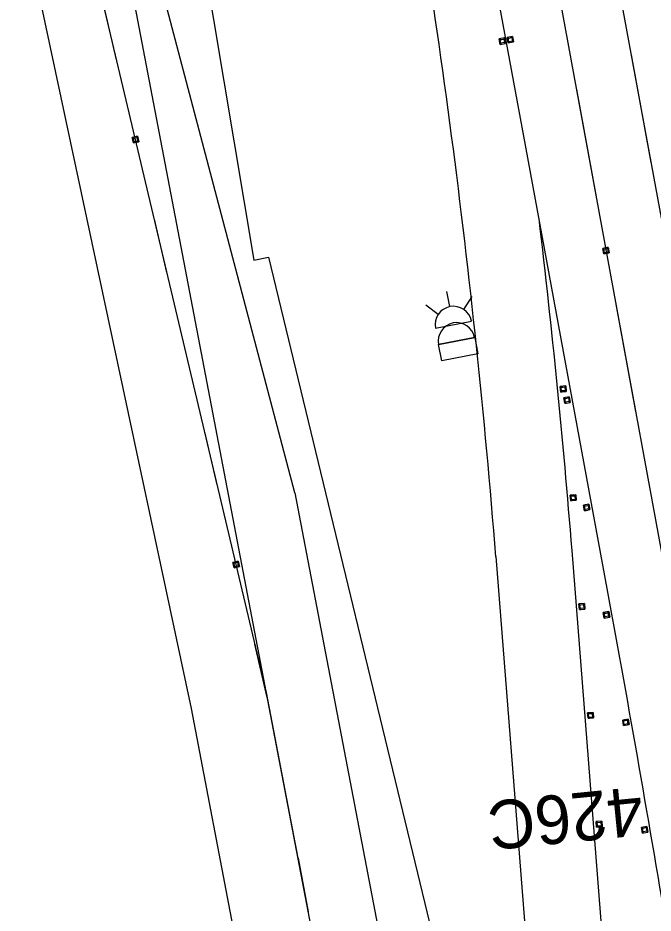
# Model space of a CAD drawing. Extents: x 2471014 to 2497726, y 6959577 to 6980268.
# Drawn here: x 2488313.2 to 2488429.6, y 6962894.6 to 6963058.6 of the extents above; entities that cross this region are included whole.
import ezdxf

# ---------------------------------------------------------------- set-up
doc = ezdxf.new("R2010")
doc.units = 0
for name, color, linetype in [('1', 7, 'Continuous'), ('13', 7, 'Continuous'), ('18', 7, 'Continuous'), ('23', 7, 'Continuous'), ('25', 7, 'Continuous'), ('5', 7, 'Continuous'), ('C-ANNO-NOTE', 7, 'Continuous'), ('C-COMM-STRC', 7, 'Continuous'), ('PMK_Pav_Mark_Wht_Number', 7, 'Continuous'), ('RDWY_PAVE_XSTREET_FOC', 7, 'Continuous'), ('V7_25', 7, 'Continuous'), ('V7_50', 7, 'Continuous')]:
    doc.layers.add(name, color=color, linetype=linetype)

msp = doc.modelspace()

# ---------------------------------------------------------------- linework, layer by layer
at = {"layer": '1'}
for p, q in [((2488331.27, 6963050.93), (2488328.96, 6963060.66)), ((2488340.48, 6963012), (2488338.18, 6963021.74)), ((2488349.7, 6962973.08), (2488347.4, 6962982.81)), ((2488358.88, 6962934.15), (2488356.61, 6962943.89)), ((2488364.5, 6962904.68), (2488366.38, 6962894.86))]:
    msp.add_line(p, q, dxfattribs=at)
at = {"layer": '13'}
for q in [(2488338.38, 6963068.57), (2488382.89, 6962872.4)]:
    msp.add_line((2488363.93, 6962971.65), q, dxfattribs=at)
at = {"layer": '18'}
for p, q in [((2488345.01, 6962932.12), (2488316.74, 6963064.61)), ((2488400.75, 6962959.93), (2488406.46, 6962887.6)), ((2488357.35, 6962867.52), (2488345.01, 6962932.12))]:
    msp.add_line(p, q, dxfattribs=at)
msp.add_arc((2486905.4, 6962841.87), 1500, 4.51393, 10.43537, dxfattribs=at)
at = {"layer": '23'}
for p, q in [((2488403.81, 6963055.23), (2488402.81, 6963055.05)), ((2488403.67, 6963055.04), (2488403.81, 6963055.23)), ((2488403.81, 6963055.23), (2488403.99, 6963054.24)), ((2488402.33, 6963054.96), (2488401.34, 6963054.78)), ((2488401.52, 6963053.78), (2488401.34, 6963054.78)), ((2488401.34, 6963054.78), (2488401.52, 6963054.64)), ((2488401.52, 6963054.64), (2488401.66, 6963054.67)), ((2488401.65, 6963053.98), (2488401.52, 6963053.78)), ((2488401.52, 6963053.78), (2488401.79, 6963053.83)), ((2488402.31, 6963054.1), (2488401.65, 6963053.98)), ((2488401.66, 6963054.67), (2488402.19, 6963054.76)), ((2488401.79, 6963053.83), (2488402.52, 6963053.97)), ((2488402.19, 6963054.76), (2488402.33, 6963054.96)), ((2488402.52, 6963053.97), (2488402.31, 6963054.1)), ((2488402.33, 6963054.96), (2488402.52, 6963053.97)), ((2488403, 6963054.05), (2488402.81, 6963055.05)), ((2488402.81, 6963055.05), (2488403, 6963054.91)), ((2488403, 6963054.91), (2488403.14, 6963054.94)), ((2488403.12, 6963054.25), (2488403, 6963054.05)), ((2488403, 6963054.05), (2488403.26, 6963054.1)), ((2488403.79, 6963054.37), (2488403.12, 6963054.25)), ((2488403.14, 6963054.94), (2488403.67, 6963055.04)), ((2488403.26, 6963054.1), (2488403.99, 6963054.24)), ((2488403.99, 6963054.24), (2488403.79, 6963054.37)), ((2488335.11, 6963036.94), (2488334.12, 6963036.71)), ((2488334.36, 6963035.72), (2488334.12, 6963036.71)), ((2488334.12, 6963036.71), (2488334.32, 6963036.58)), ((2488334.32, 6963036.58), (2488334.46, 6963036.62)), ((2488334.47, 6963035.92), (2488334.36, 6963035.72)), ((2488334.36, 6963035.72), (2488334.62, 6963035.79)), ((2488334.46, 6963036.62), (2488334.98, 6963036.74)), ((2488335.13, 6963036.08), (2488334.47, 6963035.92)), ((2488334.62, 6963035.79), (2488335.34, 6963035.96)), ((2488334.98, 6963036.74), (2488335.11, 6963036.94)), ((2488335.11, 6963036.94), (2488335.34, 6963035.96)), ((2488335.34, 6963035.96), (2488335.13, 6963036.08)), ((2488421.06, 6963016.55), (2488420.33, 6963016.41)), ((2488420.51, 6963015.42), (2488420.33, 6963016.41)), ((2488420.33, 6963016.41), (2488420.54, 6963016.28)), ((2488420.54, 6963016.28), (2488421.2, 6963016.4)), ((2488421.33, 6963016.6), (2488421.06, 6963016.55)), ((2488421.2, 6963016.4), (2488421.33, 6963016.6)), ((2488421.33, 6963016.6), (2488421.51, 6963015.6)), ((2488420.66, 6963015.62), (2488420.51, 6963015.42)), ((2488420.51, 6963015.42), (2488421.51, 6963015.6)), ((2488421.19, 6963015.71), (2488420.66, 6963015.62)), ((2488421.32, 6963015.74), (2488421.19, 6963015.71)), ((2488421.51, 6963015.6), (2488421.32, 6963015.74)), ((2488413.55, 6962991.2), (2488412.54, 6962991.1)), ((2488413.39, 6962991.02), (2488413.55, 6962991.2)), ((2488413.55, 6962991.2), (2488413.65, 6962990.19)), ((2488412.64, 6962990.09), (2488412.54, 6962991.1)), ((2488412.54, 6962991.1), (2488412.71, 6962990.95)), ((2488412.78, 6962990.28), (2488412.64, 6962990.09)), ((2488412.64, 6962990.09), (2488412.9, 6962990.12)), ((2488412.71, 6962990.95), (2488412.85, 6962990.96)), ((2488413.45, 6962990.34), (2488412.78, 6962990.28)), ((2488412.85, 6962990.96), (2488413.39, 6962991.02)), ((2488412.9, 6962990.12), (2488413.65, 6962990.19)), ((2488413.65, 6962990.19), (2488413.45, 6962990.34)), ((2488414.19, 6962989.2), (2488413.19, 6962989.02)), ((2488413.38, 6962988.02), (2488413.19, 6962989.02)), ((2488413.19, 6962989.02), (2488413.38, 6962988.88)), ((2488413.38, 6962988.88), (2488413.52, 6962988.91)), ((2488413.5, 6962988.21), (2488413.38, 6962988.02)), ((2488413.38, 6962988.02), (2488413.64, 6962988.07)), ((2488414.17, 6962988.34), (2488413.5, 6962988.21)), ((2488413.52, 6962988.91), (2488414.05, 6962989)), ((2488413.64, 6962988.07), (2488414.38, 6962988.2)), ((2488414.05, 6962989), (2488414.19, 6962989.2)), ((2488414.38, 6962988.2), (2488414.17, 6962988.34)), ((2488414.19, 6962989.2), (2488414.38, 6962988.2)), ((2488415.39, 6962971.28), (2488414.38, 6962971.19)), ((2488414.46, 6962970.18), (2488414.38, 6962971.19)), ((2488414.38, 6962971.19), (2488414.55, 6962971.04)), ((2488414.61, 6962970.36), (2488414.46, 6962970.18)), ((2488414.46, 6962970.18), (2488414.73, 6962970.21)), ((2488414.55, 6962971.04), (2488414.69, 6962971.05)), ((2488415.28, 6962970.42), (2488414.61, 6962970.36)), ((2488414.69, 6962971.05), (2488415.22, 6962971.1)), ((2488414.73, 6962970.21), (2488415.47, 6962970.27)), ((2488415.22, 6962971.1), (2488415.39, 6962971.28)), ((2488415.47, 6962970.27), (2488415.28, 6962970.42)), ((2488415.39, 6962971.28), (2488415.47, 6962970.27)), ((2488417.81, 6962969.53), (2488416.82, 6962969.35)), ((2488417, 6962968.35), (2488416.82, 6962969.35)), ((2488416.82, 6962969.35), (2488417, 6962969.21)), ((2488417, 6962969.21), (2488417.14, 6962969.24)), ((2488417.13, 6962968.55), (2488417, 6962968.35)), ((2488417, 6962968.35), (2488417.27, 6962968.4)), ((2488417.79, 6962968.67), (2488417.13, 6962968.55)), ((2488417.14, 6962969.24), (2488417.67, 6962969.33)), ((2488417.27, 6962968.4), (2488418, 6962968.54)), ((2488417.67, 6962969.33), (2488417.81, 6962969.53)), ((2488418, 6962968.54), (2488417.79, 6962968.67)), ((2488417.81, 6962969.53), (2488418, 6962968.54)), ((2488353.54, 6962959.1), (2488352.55, 6962958.86)), ((2488352.79, 6962957.88), (2488352.55, 6962958.86)), ((2488352.55, 6962958.86), (2488352.75, 6962958.74)), ((2488352.75, 6962958.74), (2488352.89, 6962958.77)), ((2488352.89, 6962958.77), (2488353.41, 6962958.89)), ((2488353.41, 6962958.89), (2488353.54, 6962959.1)), ((2488353.54, 6962959.1), (2488353.78, 6962958.11)), ((2488352.9, 6962958.08), (2488352.79, 6962957.88)), ((2488352.79, 6962957.88), (2488353.05, 6962957.94)), ((2488353.56, 6962958.23), (2488352.9, 6962958.08)), ((2488353.05, 6962957.94), (2488353.78, 6962958.11)), ((2488353.78, 6962958.11), (2488353.56, 6962958.23)), ((2488416.99, 6962951.34), (2488415.98, 6962951.26)), ((2488416.06, 6962950.25), (2488415.98, 6962951.26)), ((2488415.98, 6962951.26), (2488416.16, 6962951.11)), ((2488416.21, 6962950.43), (2488416.06, 6962950.25)), ((2488416.06, 6962950.25), (2488416.33, 6962950.27)), ((2488416.16, 6962951.11), (2488416.3, 6962951.12)), ((2488416.88, 6962950.48), (2488416.21, 6962950.43)), ((2488416.3, 6962951.12), (2488416.83, 6962951.16)), ((2488416.33, 6962950.27), (2488417.07, 6962950.33)), ((2488416.83, 6962951.16), (2488416.99, 6962951.34)), ((2488417.07, 6962950.33), (2488416.88, 6962950.48)), ((2488416.99, 6962951.34), (2488417.07, 6962950.33)), ((2488421.44, 6962949.86), (2488420.44, 6962949.68)), ((2488420.62, 6962948.68), (2488420.44, 6962949.68)), ((2488420.44, 6962949.68), (2488420.63, 6962949.54)), ((2488420.75, 6962948.88), (2488420.62, 6962948.68)), ((2488420.62, 6962948.68), (2488420.89, 6962948.73)), ((2488420.63, 6962949.54), (2488420.76, 6962949.57)), ((2488421.41, 6962949), (2488420.75, 6962948.88)), ((2488420.76, 6962949.57), (2488421.29, 6962949.66)), ((2488420.89, 6962948.73), (2488421.62, 6962948.87)), ((2488421.29, 6962949.66), (2488421.44, 6962949.86)), ((2488421.62, 6962948.87), (2488421.41, 6962949)), ((2488421.44, 6962949.86), (2488421.62, 6962948.87)), ((2488418.57, 6962931.4), (2488417.56, 6962931.32)), ((2488417.64, 6962930.31), (2488417.56, 6962931.32)), ((2488417.56, 6962931.32), (2488417.73, 6962931.17)), ((2488417.73, 6962931.17), (2488417.87, 6962931.18)), ((2488418.46, 6962930.55), (2488417.78, 6962930.49)), ((2488417.87, 6962931.18), (2488418.41, 6962931.22)), ((2488418.41, 6962931.22), (2488418.57, 6962931.4)), ((2488418.65, 6962930.39), (2488418.46, 6962930.55)), ((2488418.57, 6962931.4), (2488418.65, 6962930.39)), ((2488417.78, 6962930.49), (2488417.64, 6962930.31)), ((2488417.64, 6962930.31), (2488417.91, 6962930.33)), ((2488417.91, 6962930.33), (2488418.65, 6962930.39)), ((2488424.99, 6962930.18), (2488423.99, 6962930)), ((2488424.16, 6962929), (2488423.99, 6962930)), ((2488423.99, 6962930), (2488424.17, 6962929.86)), ((2488424.29, 6962929.19), (2488424.16, 6962929)), ((2488424.16, 6962929), (2488424.43, 6962929.05)), ((2488424.17, 6962929.86), (2488424.31, 6962929.89)), ((2488424.96, 6962929.31), (2488424.29, 6962929.19)), ((2488424.31, 6962929.89), (2488424.84, 6962929.98)), ((2488424.43, 6962929.05), (2488425.16, 6962929.18)), ((2488424.84, 6962929.98), (2488424.99, 6962930.18)), ((2488425.16, 6962929.18), (2488424.96, 6962929.31)), ((2488424.99, 6962930.18), (2488425.16, 6962929.18)), ((2488420.14, 6962911.47), (2488419.13, 6962911.39)), ((2488419.21, 6962910.37), (2488419.13, 6962911.39)), ((2488419.13, 6962911.39), (2488419.3, 6962911.23)), ((2488419.3, 6962911.23), (2488419.44, 6962911.24)), ((2488419.44, 6962911.24), (2488419.98, 6962911.28)), ((2488419.98, 6962911.28), (2488420.14, 6962911.47)), ((2488420.14, 6962911.47), (2488420.22, 6962910.45)), ((2488419.36, 6962910.55), (2488419.21, 6962910.37)), ((2488419.21, 6962910.37), (2488419.48, 6962910.4)), ((2488420.03, 6962910.61), (2488419.36, 6962910.55)), ((2488419.48, 6962910.4), (2488420.22, 6962910.45)), ((2488420.22, 6962910.45), (2488420.03, 6962910.61)), ((2488428.43, 6962910.47), (2488427.43, 6962910.3)), ((2488427.6, 6962909.3), (2488427.43, 6962910.3)), ((2488427.43, 6962910.3), (2488427.61, 6962910.16)), ((2488427.73, 6962909.49), (2488427.6, 6962909.3)), ((2488427.6, 6962909.3), (2488427.87, 6962909.35)), ((2488427.61, 6962910.16), (2488427.75, 6962910.19)), ((2488428.4, 6962909.61), (2488427.73, 6962909.49)), ((2488427.75, 6962910.19), (2488428.28, 6962910.28)), ((2488427.87, 6962909.35), (2488428.6, 6962909.47)), ((2488428.28, 6962910.28), (2488428.43, 6962910.47)), ((2488428.6, 6962909.47), (2488428.4, 6962909.61)), ((2488428.43, 6962910.47), (2488428.6, 6962909.47))]:
    msp.add_line(p, q, dxfattribs=at)
for points in [[(2488401.65, 6963053.98), (2488401.52, 6963054.64), (2488402.19, 6963054.76), (2488402.31, 6963054.1)], [(2488403.12, 6963054.25), (2488403, 6963054.91), (2488403.67, 6963055.04), (2488403.79, 6963054.37)], [(2488334.47, 6963035.92), (2488334.32, 6963036.58), (2488334.98, 6963036.74), (2488335.13, 6963036.08)], [(2488421.2, 6963016.4), (2488421.32, 6963015.74), (2488420.66, 6963015.62), (2488420.54, 6963016.28)], [(2488412.78, 6962990.28), (2488412.71, 6962990.95), (2488413.39, 6962991.02), (2488413.45, 6962990.34)], [(2488413.5, 6962988.21), (2488413.38, 6962988.88), (2488414.05, 6962989), (2488414.17, 6962988.34)], [(2488414.61, 6962970.36), (2488414.55, 6962971.04), (2488415.22, 6962971.1), (2488415.28, 6962970.42)], [(2488417.13, 6962968.55), (2488417, 6962969.21), (2488417.67, 6962969.33), (2488417.79, 6962968.67)], [(2488352.9, 6962958.08), (2488352.75, 6962958.74), (2488353.41, 6962958.89), (2488353.56, 6962958.23)], [(2488416.21, 6962950.43), (2488416.16, 6962951.11), (2488416.83, 6962951.16), (2488416.88, 6962950.48)], [(2488420.75, 6962948.88), (2488420.63, 6962949.54), (2488421.29, 6962949.66), (2488421.41, 6962949)], [(2488417.78, 6962930.49), (2488417.73, 6962931.17), (2488418.41, 6962931.22), (2488418.46, 6962930.55)], [(2488424.29, 6962929.19), (2488424.17, 6962929.86), (2488424.84, 6962929.98), (2488424.96, 6962929.31)], [(2488419.36, 6962910.55), (2488419.3, 6962911.23), (2488419.98, 6962911.28), (2488420.03, 6962910.61)], [(2488427.73, 6962909.49), (2488427.61, 6962910.16), (2488428.28, 6962910.28), (2488428.4, 6962909.61)]]:
    msp.add_lwpolyline(points, close=True, dxfattribs=at)
at = {"layer": '25'}
for p, q in [((2488421.28, 6962953.41), (2488406.19, 6963035.33)), ((2488420.32, 6962889.91), (2488414.71, 6962961.03))]:
    msp.add_line(p, q, dxfattribs=at)
for centre, radius, start, end in [((2486905.4, 6962841.87), 1514, 4.51393, 6.82786), ((2484825.75, 6962291.21), 3656, 9.41605, 10.43537)]:
    msp.add_arc(centre, radius, start, end, dxfattribs=at)
at = {"layer": '5'}
msp.add_line((2488406.19, 6963035.33), (2488351.85, 6963330.37), dxfattribs=at)
at = {"layer": 'C-ANNO-NOTE'}
msp.add_line((2488371.12, 6962870.04), (2488281.3, 6963340.31), dxfattribs=at)
at = {"layer": 'C-COMM-STRC'}
for p, q in [((2488392.34, 6963005.75), (2488391.8, 6963008.51)), ((2488390.18, 6963004.32), (2488387.92, 6963005.98)), ((2488394.87, 6963005.23), (2488396.41, 6963007.58)), ((2488389.67, 6963001.79), (2488396.3, 6963003.08)), ((2488396.88, 6963000.08), (2488390.25, 6962998.79)), ((2488390.25, 6962998.79), (2488396.88, 6963000.08))]:
    msp.add_line(p, q, dxfattribs=at)
msp.add_lwpolyline([(2488396.88, 6963000.08), (2488397.46, 6962997.08), (2488390.83, 6962995.79), (2488390.25, 6962998.79)], close=True, dxfattribs=at)
for centre in [(2488392.98, 6963002.43), (2488393.56, 6962999.43)]:
    msp.add_arc(centre, 3.37, 10.983, 190.983, dxfattribs=at)
at = {"layer": 'RDWY_PAVE_XSTREET_FOC'}
for p, q in [((2488425.52, 6963051.84), (2488429.14, 6963032.17)), ((2488415.5, 6963045.51), (2488419.12, 6963025.84)), ((2488422.74, 6963006.18), (2488426.36, 6962986.51))]:
    msp.add_line(p, q, dxfattribs=at)
at = {"layer": 'V7_25'}
for p, q in [((2488370.16, 6963352.42), (2488442.91, 6962957.39)), ((2488359.34, 6963350.43), (2488432.09, 6962955.4)), ((2488358.71, 6962935.04), (2488327.56, 6963066.59)), ((2488364.5, 6962904.68), (2488358.71, 6962935.04))]:
    msp.add_line(p, q, dxfattribs=at)
at = {"layer": 'V7_50'}
msp.add_lwpolyline([(2488180.28, 6963834.39), (2488180.96, 6963804.18), (2488182.56, 6963770.39), (2488185.31, 6963735.54), (2488188.02, 6963709.85), (2488201.8, 6963602.24), (2488185.27, 6963601.98), (2488186.11, 6963551.49), (2488186.27, 6963541.99), (2488204.14, 6963542.29), (2488216.07, 6963532.64), (2488236.2, 6963424.83), (2488269.12, 6963431.42), (2488300.81, 6963286.42), (2488310.38, 6963289.04), (2488356.41, 6963014.27), (2488359.09, 6963014.77), (2488390.92, 6962883.25)], dxfattribs=at)

# ---------------------------------------------------------------- texts
at = {"layer": 'PMK_Pav_Mark_Wht_Number'}
msp.add_text('426C', height=8.9, rotation=185.6583, dxfattribs=at).set_placement((2488427.26, 6962917.81))

doc.saveas('drawing.dxf')
